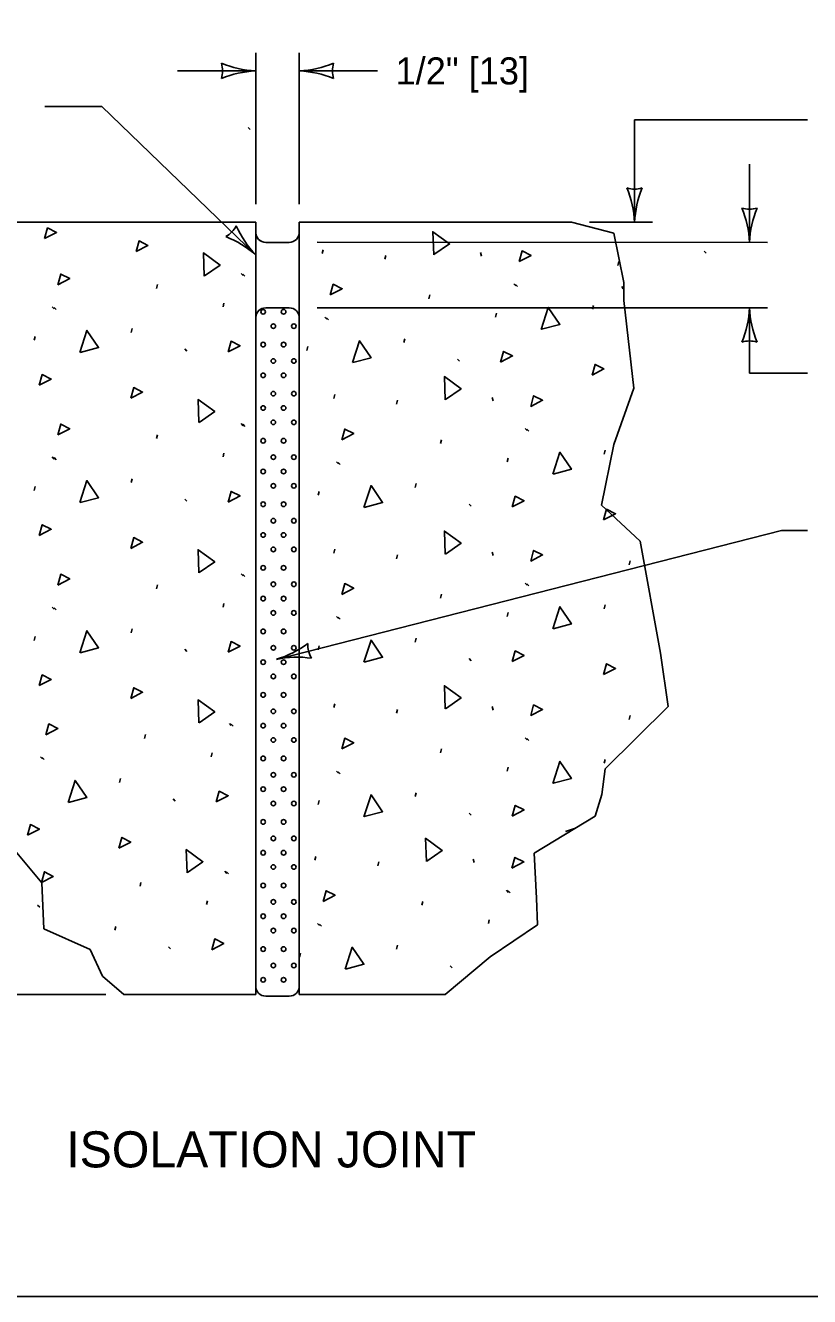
# Model space of a CAD drawing. Extents: x 49979.1 to 50021, y 49966.7 to 50011.4.
# Drawn here: x 50007.273 to 50009.012, y 49987.799 to 49990.616 of the extents above; entities that cross this region are included whole.
import ezdxf

# ---------------------------------------------------------------- set-up
doc = ezdxf.new("R2010")
doc.units = 0
for name, color, linetype in [('Level 1', 7, 'Continuous'), ('Level 12', 7, 'Continuous'), ('Level 13', 7, 'Continuous'), ('Level 2', 7, 'Continuous'), ('Level 3', 7, 'Continuous')]:
    doc.layers.add(name, color=color, linetype=linetype)

msp = doc.modelspace()

# ---------------------------------------------------------------- linework, layer by layer
at = {"layer": 'Level 1'}
for p, q in [((50007.1292, 49990.1802), (50007.7836, 49990.1802)), ((50007.7836, 49990.1802), (50007.7836, 49988.4683)), ((50007.8803, 49990.1802), (50008.4844, 49990.1802)), ((50007.8803, 49990.1802), (50007.8803, 49988.4683)), ((50008.5783, 49990.156), (50008.4844, 49990.1802)), ((50007.7836, 49989.9237), (50007.7836, 49990.1579)), ((50008.6003, 49990.0464), (50008.5783, 49990.156)), ((50007.8059, 49990.1356), (50007.858, 49990.1356)), ((50008.6003, 49990.0065), (50008.6003, 49990.0464)), ((50008.6222, 49989.8122), (50008.6003, 49990.0065)), ((50007.8059, 49989.9904), (50007.858, 49989.9904)), ((50008.5783, 49989.6876), (50008.6222, 49989.8122)), ((50008.551, 49989.553), (50008.5783, 49989.6876)), ((50008.6364, 49989.473), (50008.551, 49989.553)), ((50008.6814, 49989.2252), (50008.6364, 49989.473)), ((50008.6989, 49989.107), (50008.6814, 49989.2252)), ((50008.5589, 49988.9683), (50008.6989, 49989.107)), ((50008.5514, 49988.9114), (50008.5589, 49988.9683)), ((50008.5364, 49988.8637), (50008.5514, 49988.9114)), ((50008.4014, 49988.7818), (50008.5364, 49988.8637)), ((50007.2238, 49988.8182), (50007.3089, 49988.7159)), ((50008.4064, 49988.6818), (50008.4014, 49988.7818)), ((50007.3089, 49988.7159), (50007.3138, 49988.6136)), ((50008.4089, 49988.6227), (50008.4064, 49988.6818)), ((50007.3138, 49988.6136), (50007.4163, 49988.5681)), ((50008.3039, 49988.5522), (50008.4089, 49988.6227)), ((50007.4163, 49988.5681), (50007.4438, 49988.509)), ((50008.2039, 49988.4683), (50008.3039, 49988.5522)), ((50007.4438, 49988.509), (50007.4913, 49988.4683)), ((50007.4913, 49988.4683), (50007.7836, 49988.4683)), ((50007.8059, 49988.4645), (50007.858, 49988.4645)), ((50007.8803, 49988.4683), (50008.2039, 49988.4683))]:
    msp.add_line(p, q, dxfattribs=at)
msp.add_lwpolyline([(49999.3835, 49998.9992), (50016.7501, 49998.9992), (50016.7501, 49987.7988), (49999.3835, 49987.7988)], close=True, dxfattribs=at)
for centre, start, end in [((50007.8059, 49990.1579), 180, 270), ((50007.858, 49990.1579), 270, 360), ((50007.8059, 49989.9681), 90, 180), ((50007.858, 49989.9681), 0, 90), ((50007.8059, 49988.4869), 180, 270), ((50007.858, 49988.4869), 270, 360)]:
    msp.add_arc(centre, 0.0223, start, end, dxfattribs=at)
at = {"layer": 'Level 12'}
msp.add_line((50008.5958, 49990.0378), (50008.599, 49990.0329), dxfattribs=at)
msp.add_lwpolyline([(50008.4907, 49988.836), (50008.4711, 49988.8299)], dxfattribs=at)
at = {"layer": 'Level 13'}
for p, q in [((50007.767, 49990.3901), (50007.7714, 49990.3855)), ((50007.8803, 49989.9681), (50007.8803, 49990.1579)), ((50007.858, 49990.1356), (50007.8059, 49990.1356)), ((50007.9311, 49990.1105), (50007.9332, 49990.119)), ((50008.7786, 49990.1164), (50008.7831, 49990.1117)), ((50008.0704, 49990.0981), (50008.0725, 49990.1066)), ((50008.2822, 49990.1128), (50008.2844, 49990.1051)), ((50008.5868, 49990.0846), (50008.5889, 49990.0931)), ((50007.7513, 49990.0665), (50007.7557, 49990.0619)), ((50007.7552, 49990.0652), (50007.7596, 49990.0605)), ((50007.5633, 49990.0334), (50007.5654, 49990.0419)), ((50008.3559, 49990.0439), (50008.3603, 49990.0392)), ((50008.3597, 49990.0425), (50008.3641, 49990.0379)), ((50008.1678, 49990.0107), (50008.17, 49990.0192)), ((50007.3324, 49989.9927), (50007.3368, 49989.988)), ((50007.3362, 49989.9913), (50007.3407, 49989.9867)), ((50007.7111, 49989.9926), (50007.7132, 49990.0011)), ((50007.8059, 49989.9904), (50007.858, 49989.9904)), ((50008.3157, 49989.9699), (50008.3178, 49989.9784)), ((50008.5309, 49989.9872), (50008.533, 49989.9956)), ((50007.937, 49989.97), (50007.9414, 49989.9654)), ((50007.9408, 49989.9686), (50007.9452, 49989.964)), ((50007.2922, 49989.9187), (50007.2943, 49989.9272)), ((50007.5074, 49989.9359), (50007.5095, 49989.9444)), ((50008.112, 49989.9133), (50008.1141, 49989.9218)), ((50007.6266, 49989.8993), (50007.631, 49989.8946)), ((50007.8968, 49989.8961), (50007.8989, 49989.9046)), ((50008.2312, 49989.8766), (50008.2356, 49989.872)), ((50007.9567, 49989.7895), (50007.9588, 49989.798)), ((50008.096, 49989.7771), (50008.0981, 49989.7856)), ((50008.3078, 49989.7918), (50008.31, 49989.7841)), ((50007.7513, 49989.7337), (50007.7557, 49989.7291)), ((50007.7552, 49989.7323), (50007.7596, 49989.7277)), ((50008.3815, 49989.7229), (50008.3859, 49989.7182)), ((50007.5633, 49989.7006), (50007.5654, 49989.709)), ((50008.1934, 49989.6897), (50008.1955, 49989.6982)), ((50008.3853, 49989.7215), (50008.3897, 49989.7169)), ((50007.7111, 49989.6598), (50007.7132, 49989.6683)), ((50008.5565, 49989.6661), (50008.5586, 49989.6746)), ((50007.3324, 49989.6598), (50007.3368, 49989.6552)), ((50007.3362, 49989.6585), (50007.3407, 49989.6538)), ((50007.9625, 49989.649), (50007.967, 49989.6444)), ((50007.9664, 49989.6476), (50007.9708, 49989.643)), ((50008.3413, 49989.6489), (50008.3434, 49989.6574)), ((50007.5074, 49989.6031), (50007.5095, 49989.6116)), ((50007.2922, 49989.5859), (50007.2943, 49989.5944)), ((50007.9224, 49989.5751), (50007.9245, 49989.5836)), ((50008.1376, 49989.5923), (50008.1397, 49989.6008)), ((50007.6266, 49989.5664), (50007.631, 49989.5618)), ((50008.2568, 49989.5556), (50008.2612, 49989.551)), ((50007.9567, 49989.4469), (50007.9588, 49989.4554)), ((50008.096, 49989.4344), (50008.0981, 49989.4429)), ((50008.3078, 49989.4491), (50008.31, 49989.4414)), ((50008.6123, 49989.4209), (50008.6145, 49989.4294)), ((50007.7513, 49989.4009), (50007.7557, 49989.3963)), ((50007.7552, 49989.3995), (50007.7596, 49989.3949)), ((50007.5633, 49989.3677), (50007.5654, 49989.3762)), ((50008.1934, 49989.347), (50008.1955, 49989.3555)), ((50008.3815, 49989.3802), (50008.3859, 49989.3756)), ((50008.3853, 49989.3788), (50008.3897, 49989.3742)), ((50007.7111, 49989.327), (50007.7132, 49989.3354)), ((50008.5565, 49989.3235), (50008.5586, 49989.332)), ((50007.3324, 49989.327), (50007.3368, 49989.3224)), ((50007.3362, 49989.3256), (50007.3407, 49989.321)), ((50007.9625, 49989.3063), (50007.967, 49989.3017)), ((50007.9664, 49989.3049), (50007.9708, 49989.3003)), ((50008.3413, 49989.3063), (50008.3434, 49989.3148)), ((50007.5074, 49989.2703), (50007.5095, 49989.2788)), ((50007.2922, 49989.2531), (50007.2943, 49989.2616)), ((50008.1376, 49989.2496), (50008.1397, 49989.2581)), ((50007.6266, 49989.2336), (50007.631, 49989.229)), ((50007.9224, 49989.2324), (50007.9245, 49989.2409)), ((50008.2568, 49989.2129), (50008.2612, 49989.2083)), ((50007.9567, 49989.1042), (50007.9588, 49989.1127)), ((50008.3078, 49989.1065), (50008.31, 49989.0988)), ((50008.096, 49989.0918), (50008.0981, 49989.1003)), ((50008.6123, 49989.0782), (50008.6145, 49989.0867)), ((50007.7251, 49989.0691), (50007.7295, 49989.0645)), ((50007.7289, 49989.0677), (50007.7334, 49989.0631)), ((50007.537, 49989.0359), (50007.5392, 49989.0444)), ((50008.3815, 49989.0375), (50008.3859, 49989.0329)), ((50008.3853, 49989.0361), (50008.3897, 49989.0315)), ((50007.3062, 49988.9952), (50007.3106, 49988.9906)), ((50007.31, 49988.9939), (50007.3144, 49988.9892)), ((50007.6849, 49988.9952), (50007.687, 49989.0037)), ((50008.1934, 49989.0044), (50008.1955, 49989.0129)), ((50008.5565, 49988.9808), (50008.5586, 49988.9893)), ((50007.9625, 49988.9637), (50007.967, 49988.959)), ((50007.9664, 49988.9623), (50007.9708, 49988.9576)), ((50008.3413, 49988.9636), (50008.3434, 49988.9721)), ((50007.4812, 49988.9385), (50007.4833, 49988.947)), ((50008.1376, 49988.9069), (50008.1397, 49988.9154)), ((50007.6004, 49988.9018), (50007.6048, 49988.8972)), ((50007.9224, 49988.8897), (50007.9245, 49988.8982)), ((50008.2568, 49988.8702), (50008.2612, 49988.8656)), ((50007.9151, 49988.7661), (50007.9172, 49988.7746)), ((50008.2662, 49988.7684), (50008.2684, 49988.7607)), ((50007.715, 49988.7415), (50007.7194, 49988.7369)), ((50007.7188, 49988.7401), (50007.7233, 49988.7355)), ((50008.0544, 49988.7537), (50008.0565, 49988.7622)), ((50007.527, 49988.7083), (50007.5291, 49988.7168)), ((50008.3399, 49988.6994), (50008.3443, 49988.6948)), ((50008.3437, 49988.6981), (50008.3481, 49988.6934)), ((50007.2999, 49988.6663), (50007.3044, 49988.6616)), ((50007.6748, 49988.6676), (50007.6769, 49988.6761)), ((50008.1518, 49988.6663), (50008.154, 49988.6748)), ((50007.921, 49988.6256), (50007.9254, 49988.621)), ((50007.9248, 49988.6242), (50007.9292, 49988.6196)), ((50008.2997, 49988.6255), (50008.3018, 49988.634)), ((50007.4711, 49988.6109), (50007.4732, 49988.6194)), ((50007.5903, 49988.5742), (50007.5947, 49988.5696)), ((50008.096, 49988.5689), (50008.0981, 49988.5774)), ((50007.8808, 49988.5517), (50007.8829, 49988.5601)), ((50008.2152, 49988.5322), (50008.2196, 49988.5275))]:
    msp.add_line(p, q, dxfattribs=at)
for points in [[(50007.3153, 49990.1438), (50007.322, 49990.1675), (50007.3418, 49990.1575), (50007.3153, 49990.1438)], [(50007.7836, 49990.1568), (50007.7836, 49990.1075), (50007.7836, 49989.9693)], [(50007.8803, 49990.1579), (50007.8803, 49990.1579)], [(50008.1784, 49990.1078), (50008.1765, 49990.159), (50008.2135, 49990.1322), (50008.1791, 49990.1083)], [(50007.5181, 49990.1151), (50007.5247, 49990.1388), (50007.5445, 49990.1288), (50007.5181, 49990.1151)], [(50008.368, 49990.0929), (50008.3746, 49990.1166), (50008.3944, 49990.1066), (50008.368, 49990.0929)], [(50007.6694, 49990.0608), (50007.6675, 49990.112), (50007.7045, 49990.0852), (50007.6701, 49990.0613)], [(50007.3445, 49990.0417), (50007.3511, 49990.0654), (50007.3709, 49990.0554), (50007.3445, 49990.0417)], [(50007.9491, 49990.019), (50007.9557, 49990.0427), (50007.9755, 49990.0327), (50007.9491, 49990.019)], [(50008.417, 49989.9427), (50008.4327, 49989.9915), (50008.4584, 49989.9536), (50008.4179, 49989.9429)], [(50007.8803, 49989.9681), (50007.8803, 49989.9681)], [(50007.3935, 49989.8915), (50007.4093, 49989.9403), (50007.4349, 49989.9024), (50007.3944, 49989.8917)], [(50007.7224, 49989.8927), (50007.7291, 49989.9164), (50007.7489, 49989.9064), (50007.7224, 49989.8927)], [(50007.9981, 49989.8689), (50008.0138, 49989.9176), (50008.0394, 49989.8798), (50007.999, 49989.869)], [(50008.327, 49989.87), (50008.3336, 49989.8938), (50008.3534, 49989.8837), (50008.327, 49989.87)], [(50008.5297, 49989.8413), (50008.5364, 49989.865), (50008.5562, 49989.855), (50008.5297, 49989.8413)], [(50007.3035, 49989.8188), (50007.3102, 49989.8426), (50007.33, 49989.8325), (50007.3035, 49989.8188)], [(50008.2039, 49989.7868), (50008.2021, 49989.838), (50008.2391, 49989.8112), (50008.2047, 49989.7873)], [(50007.5063, 49989.7901), (50007.5129, 49989.8138), (50007.5327, 49989.8038), (50007.5063, 49989.7901)], [(50007.6575, 49989.7359), (50007.6557, 49989.7871), (50007.6927, 49989.7603), (50007.6583, 49989.7363)], [(50008.3936, 49989.7719), (50008.4002, 49989.7956), (50008.42, 49989.7856), (50008.3936, 49989.7719)], [(50007.3445, 49989.7089), (50007.3511, 49989.7326), (50007.3709, 49989.7225), (50007.3445, 49989.7089)], [(50007.9747, 49989.698), (50007.9813, 49989.7217), (50008.0011, 49989.7117), (50007.9747, 49989.698)], [(50008.4426, 49989.6217), (50008.4583, 49989.6705), (50008.4839, 49989.6326), (50008.4435, 49989.6219)], [(50007.3935, 49989.5587), (50007.4093, 49989.6075), (50007.4349, 49989.5696), (50007.3944, 49989.5588)], [(50007.7224, 49989.5599), (50007.7291, 49989.5836), (50007.7489, 49989.5736), (50007.7224, 49989.5599)], [(50008.0237, 49989.5478), (50008.0394, 49989.5966), (50008.065, 49989.5587), (50008.0245, 49989.548)], [(50008.3526, 49989.549), (50008.3592, 49989.5728), (50008.379, 49989.5627), (50008.3526, 49989.549)], [(50008.5553, 49989.5203), (50008.562, 49989.544), (50008.5818, 49989.534), (50008.5553, 49989.5203)], [(50007.3035, 49989.486), (50007.3102, 49989.5097), (50007.33, 49989.4997), (50007.3035, 49989.486)], [(50007.5063, 49989.4573), (50007.5129, 49989.481), (50007.5327, 49989.471), (50007.5063, 49989.4573)], [(50008.2039, 49989.4442), (50008.2021, 49989.4954), (50008.2391, 49989.4685), (50008.2047, 49989.4446)], [(50007.6575, 49989.403), (50007.6557, 49989.4542), (50007.6927, 49989.4274), (50007.6583, 49989.4035)], [(50008.3936, 49989.4292), (50008.4002, 49989.4529), (50008.42, 49989.4429), (50008.3936, 49989.4292)], [(50007.3445, 49989.376), (50007.3511, 49989.3998), (50007.3709, 49989.3897), (50007.3445, 49989.376)], [(50007.9747, 49989.3553), (50007.9813, 49989.3791), (50008.0011, 49989.369), (50007.9747, 49989.3553)], [(50008.4426, 49989.279), (50008.4583, 49989.3278), (50008.4839, 49989.2899), (50008.4435, 49989.2792)], [(50007.3935, 49989.2259), (50007.4093, 49989.2746), (50007.4349, 49989.2368), (50007.3944, 49989.226)], [(50007.7224, 49989.2271), (50007.7291, 49989.2508), (50007.7489, 49989.2407), (50007.7224, 49989.2271)], [(50008.0237, 49989.2052), (50008.0394, 49989.2539), (50008.065, 49989.2161), (50008.0245, 49989.2053)], [(50008.3526, 49989.2064), (50008.3592, 49989.2301), (50008.379, 49989.22), (50008.3526, 49989.2064)], [(50008.5553, 49989.1777), (50008.562, 49989.2014), (50008.5818, 49989.1913), (50008.5553, 49989.1777)], [(50007.3035, 49989.1532), (50007.3102, 49989.1769), (50007.33, 49989.1669), (50007.3035, 49989.1532)], [(50007.5063, 49989.1245), (50007.5129, 49989.1482), (50007.5327, 49989.1382), (50007.5063, 49989.1245)], [(50008.2039, 49989.1015), (50008.2021, 49989.1527), (50008.2391, 49989.1259), (50008.2047, 49989.1019)], [(50007.6575, 49989.0702), (50007.6557, 49989.1214), (50007.6927, 49989.0946), (50007.6583, 49989.0707)], [(50008.3936, 49989.0865), (50008.4002, 49989.1103), (50008.42, 49989.1002), (50008.3936, 49989.0865)], [(50007.3183, 49989.0443), (50007.3249, 49989.068), (50007.3447, 49989.0579), (50007.3183, 49989.0443)], [(50007.9747, 49989.0127), (50007.9813, 49989.0364), (50008.0011, 49989.0264), (50007.9747, 49989.0127)], [(50008.4426, 49988.9364), (50008.4583, 49988.9851), (50008.4839, 49988.9473), (50008.4435, 49988.9365)], [(50007.3673, 49988.8941), (50007.383, 49988.9428), (50007.4087, 49988.905), (50007.3682, 49988.8942)], [(50007.6962, 49988.8953), (50007.7028, 49988.919), (50007.7227, 49988.9089), (50007.6962, 49988.8953)], [(50008.0237, 49988.8625), (50008.0394, 49988.9113), (50008.065, 49988.8734), (50008.0245, 49988.8627)], [(50008.3526, 49988.8637), (50008.3592, 49988.8874), (50008.379, 49988.8774), (50008.3526, 49988.8637)], [(50007.2773, 49988.8214), (50007.2839, 49988.8451), (50007.3037, 49988.8351), (50007.2773, 49988.8214)], [(50007.48, 49988.7927), (50007.4867, 49988.8164), (50007.5065, 49988.8064), (50007.48, 49988.7927)], [(50008.1624, 49988.7634), (50008.1605, 49988.8146), (50008.1975, 49988.7878), (50008.1631, 49988.7639)], [(50007.6313, 49988.7384), (50007.6294, 49988.7896), (50007.6665, 49988.7628), (50007.6321, 49988.7389)], [(50008.352, 49988.7485), (50008.3586, 49988.7722), (50008.3784, 49988.7621), (50008.352, 49988.7485)], [(50007.3082, 49988.7167), (50007.3148, 49988.7404), (50007.3346, 49988.7303), (50007.3082, 49988.7167)], [(50007.9331, 49988.6746), (50007.9397, 49988.6983), (50007.9595, 49988.6883), (50007.9331, 49988.6746)], [(50007.6861, 49988.5677), (50007.6928, 49988.5914), (50007.7126, 49988.5814), (50007.6861, 49988.5677)], [(50007.9821, 49988.5244), (50007.9978, 49988.5732), (50008.0235, 49988.5353), (50007.983, 49988.5246)]]:
    msp.add_lwpolyline(points, dxfattribs=at)
for centre in [(50007.8228, 49989.9499), (50007.8682, 49989.9499), (50007.8228, 49989.8726), (50007.8682, 49989.8726), (50007.8001, 49989.8408), (50007.8455, 49989.8408), (50007.8228, 49989.8002), (50007.8682, 49989.8002), (50007.8001, 49989.7684), (50007.8455, 49989.7684), (50007.8228, 49989.7367), (50007.8682, 49989.7367), (50007.8228, 49989.6594), (50007.8682, 49989.6594), (50007.8001, 49989.6276), (50007.8455, 49989.6276), (50007.8228, 49989.5958), (50007.8682, 49989.5958), (50007.8228, 49989.5185), (50007.8682, 49989.5185), (50007.8001, 49989.4868), (50007.8455, 49989.4868), (50007.8228, 49989.455), (50007.8682, 49989.455), (50007.8228, 49989.3777), (50007.8682, 49989.3777), (50007.8001, 49989.3459), (50007.8455, 49989.3459), (50007.8228, 49989.3142), (50007.8682, 49989.3142), (50007.8228, 49989.2369), (50007.8682, 49989.2369), (50007.8001, 49989.2051), (50007.8455, 49989.2051), (50007.8228, 49989.1734), (50007.8682, 49989.1734), (50007.8228, 49989.0961), (50007.8682, 49989.0961), (50007.8001, 49989.0643), (50007.8455, 49989.0643), (50007.8228, 49989.0325), (50007.8682, 49989.0325), (50007.8228, 49988.9552), (50007.8682, 49988.9552), (50007.8001, 49988.9235), (50007.8455, 49988.9235), (50007.8228, 49988.8917), (50007.8682, 49988.8917), (50007.8228, 49988.8144), (50007.8682, 49988.8144), (50007.8001, 49988.7826), (50007.8455, 49988.7826), (50007.8228, 49988.7509), (50007.8682, 49988.7509), (50007.8228, 49988.6736), (50007.8682, 49988.6736), (50007.8001, 49988.6418), (50007.8455, 49988.6418), (50007.8228, 49988.6101), (50007.8682, 49988.6101), (50007.8228, 49988.5327), (50007.8682, 49988.5327), (50007.8001, 49988.501), (50007.8455, 49988.501)]:
    msp.add_circle(centre, 0.00507, dxfattribs=at)
for centre, radius, start, end in [((50007.8059, 49990.1579), 0.0223, 182.9692, 270), ((50007.858, 49990.1579), 0.0223, 270, 360), ((50007.8059, 49989.9681), 0.0223, 90, 177.0308), ((50007.8001, 49989.9816), 0.00507, 0.9416, 0), ((50007.8455, 49989.9818), 0.00507, 0, 180), ((50007.8455, 49989.9816), 0.00507, 180, 0), ((50007.858, 49989.9681), 0.0223, 360, 90), ((50007.8001, 49989.909), 0.00507, 0, 180), ((50007.8001, 49989.9089), 0.00507, 180, 0), ((50007.8455, 49989.909), 0.00507, 0, 180), ((50007.8455, 49989.9089), 0.00507, 180, 0), ((50007.8001, 49989.6958), 0.00507, 0, 180), ((50007.8001, 49989.6957), 0.00507, 180, 0), ((50007.8455, 49989.6958), 0.00507, 0, 180), ((50007.8455, 49989.6957), 0.00507, 180, 0), ((50007.8001, 49989.555), 0.00507, 0, 180), ((50007.8001, 49989.5548), 0.00507, 180, 0), ((50007.8455, 49989.555), 0.00507, 0, 180), ((50007.8455, 49989.5548), 0.00507, 180, 0), ((50007.8001, 49989.4142), 0.00507, 0, 180), ((50007.8001, 49989.414), 0.00507, 180, 0), ((50007.8455, 49989.4142), 0.00507, 0, 180), ((50007.8455, 49989.414), 0.00507, 180, 0), ((50007.8001, 49989.2733), 0.00507, 0, 180), ((50007.8001, 49989.2732), 0.00507, 180, 0), ((50007.8455, 49989.2733), 0.00507, 0, 180), ((50007.8455, 49989.2732), 0.00507, 180, 0), ((50007.8001, 49989.1325), 0.00507, 0, 180), ((50007.8001, 49989.1324), 0.00507, 180, 0), ((50007.8455, 49989.1325), 0.00507, 0, 180), ((50007.8455, 49989.1324), 0.00507, 180, 0), ((50007.8001, 49988.9917), 0.00507, 0, 180), ((50007.8001, 49988.9915), 0.00507, 180, 0), ((50007.8455, 49988.9917), 0.00507, 0, 180), ((50007.8455, 49988.9915), 0.00507, 180, 0), ((50007.8001, 49988.8509), 0.00507, 0, 180), ((50007.8001, 49988.8507), 0.00507, 180, 0), ((50007.8455, 49988.8509), 0.00507, 0, 180), ((50007.8455, 49988.8507), 0.00507, 180, 0), ((50007.8001, 49988.71), 0.00507, 0, 180), ((50007.8001, 49988.7099), 0.00507, 180, 0), ((50007.8455, 49988.71), 0.00507, 0, 180), ((50007.8455, 49988.7099), 0.00507, 180, 0), ((50007.8001, 49988.5692), 0.00507, 0, 180), ((50007.8001, 49988.569), 0.00507, 180, 0), ((50007.8455, 49988.5692), 0.00507, 0, 180), ((50007.8455, 49988.569), 0.00507, 180, 0)]:
    msp.add_arc(centre, radius, start, end, dxfattribs=at)
at = {"layer": 'Level 3'}
for p, q in [((50007.7836, 49990.2202), (50007.7836, 49990.5556)), ((50007.8803, 49990.2202), (50007.8803, 49990.5556)), ((50007.7836, 49990.5156), (50007.6101, 49990.5156)), ((50008.0538, 49990.5156), (50007.8803, 49990.5156)), ((50007.442, 49990.437), (50007.316, 49990.437)), ((50007.442, 49990.437), (50007.7836, 49990.1075)), ((50008.6239, 49990.4074), (50009.0075, 49990.4073)), ((50008.6239, 49990.1802), (50008.6239, 49990.4074)), ((50008.8789, 49990.1356), (50008.8789, 49990.309)), ((50008.6639, 49990.1802), (50008.5244, 49990.1802)), ((50008.9189, 49990.1356), (50007.9203, 49990.1357)), ((50008.9189, 49989.9904), (50007.9203, 49989.9905)), ((50008.8789, 49989.8453), (50008.8789, 49989.9904)), ((50009.0075, 49989.8453), (50008.8789, 49989.8453)), ((50007.8296, 49989.2113), (50008.9498, 49989.4969)), ((50009.0075, 49989.4969), (50008.9498, 49989.4969)), ((50007.4513, 49988.4683), (50006.5116, 49988.4683))]:
    msp.add_line(p, q, dxfattribs=at)
for centre, radius, start, end in [((50007.7927, 49990.7378), 0.2223, 247.456, 267.6395), ((50007.6553, 49990.5156), 0.0548, 342.1388, 17.8612), ((50007.7951, 49990.2829), 0.233, 92.8273, 112.0772), ((50007.8712, 49990.7378), 0.2223, 272.3605, 292.544), ((50007.8688, 49990.2829), 0.233, 67.9228, 87.1727), ((50008.0085, 49990.5156), 0.0548, 162.1388, 197.8612), ((50008.4018, 49990.1711), 0.2223, 2.3605, 22.544), ((50008.6239, 49990.3084), 0.0548, 252.1388, 287.8612), ((50008.8567, 49990.1687), 0.233, 157.9228, 177.1727), ((50008.6568, 49990.1264), 0.2223, 2.3605, 22.544), ((50008.8789, 49990.2638), 0.0548, 252.1388, 287.8612), ((50009.1116, 49990.1241), 0.233, 157.9228, 177.1727), ((50007.6913, 49990.1966), 0.0548, 298.176, 333.8984), ((50007.9534, 49990.2671), 0.233, 203.96, 223.2099), ((50007.636, 49989.9413), 0.2223, 48.3977, 68.5812), ((50008.6568, 49989.9996), 0.2223, 337.456, 357.6395), ((50009.1116, 49990.0019), 0.233, 182.8273, 202.0772), ((50008.8789, 49989.8622), 0.0548, 72.1388, 107.8612), ((50007.761, 49989.434), 0.233, 287.1287, 306.3785), ((50007.9538, 49989.243), 0.0548, 176.4402, 212.1625), ((50007.8756, 49988.9938), 0.2223, 81.7574, 101.9409)]:
    msp.add_arc(centre, radius, start, end, dxfattribs=at)

# ---------------------------------------------------------------- texts
at = {"layer": 'Level 2'}
for s, height, p in [('1/2" [13] ', 0.06, (50008.0938, 49990.4856)), ('ISOLATION JOINT', 0.08, (50007.3633, 49988.0851))]:
    msp.add_text(s, height=height, dxfattribs=at).set_placement(p)

doc.saveas('drawing.dxf')
